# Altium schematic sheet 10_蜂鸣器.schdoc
size 309 x 223 mm; Symbol: Sheet-Symbol_A4; Device: Sheet-Symbol_A4; Company: 嘉立创EDA; Version: V1.0; Page Size: A4; @Project Name: 共享电动车中控; @Page Count: 11; @Update Date: 2024-11-20; @Create Date: 2024-10-05; @Schematic Name: SCH; @Page No: 10; @Page Name: 蜂鸣器; @Board Name: STM32F103C8T6; @Create Time: 01:14:23; @Update Time: 22:56:27
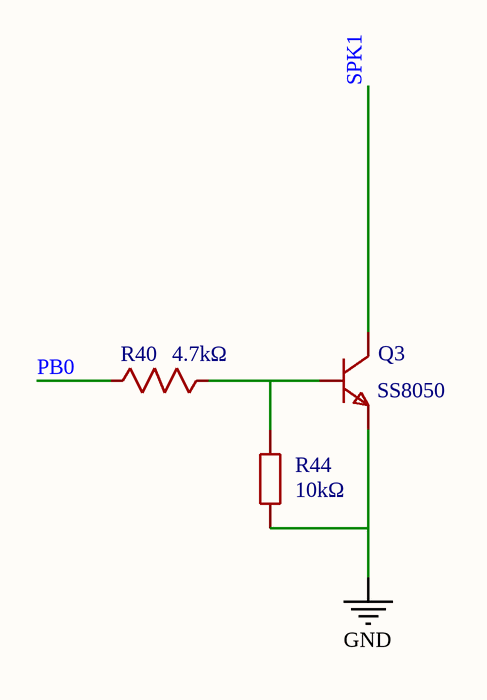
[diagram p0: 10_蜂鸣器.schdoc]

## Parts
Q3  SS8050  [SOT-23-3_L2.9-W1.3-P1.90-LS2.4-BR]  (value not drawn)
R40  4.7kΩ  [R0805]  (value not drawn)
R44  10kΩ  [R0805]

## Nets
GND: Q3.2(E) R44.2
PB0: R40.1
SPK1: Q3.3(C)
NetQ3_1: Q3.1(B) R40.2 R44.1

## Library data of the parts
Q3 = SS8050_C7420370: 晶体管类型:NPN;集电极电流(Ic):1.5A;集射极击穿电压(Vceo):25V;功率(Pd):300mW;直流电流增益(hFE@Ic,Vce):120@100mA,1.0V;; Manufacturer: 宏迦橙; Add into BOM: yes; Transistor Type: NPN; Collector Current (Ic): 1.5A; Collector-Emitter Breakdown Voltage (Vceo): 25V; Power Dissipation (Pd): 300mW; Transition Frequency (fT): 100MHz; Collector Cut-Off Current (Icbo): 100nA; Collector-Emitter Saturation Voltage (VCE(sat)@Ic,Ib): 500mV@800mA,80mA
R40 = 0805W8F4701T5E: 电阻类型:厚膜电阻;阻值:4.7kΩ;精度:±1%;功率:125mW;最大工作电压:150V;温度系数:±100ppm/℃;; Manufacturer: UNI-ROYAL(厚声); Symbol: 4.7k; Add into BOM: yes; Tolerance: ±1%; Power(Watts): 125mW; Overload Voltage (Max): 150V; Origin Footprint: R0603
R44 = 0805W8F1002T5E_C17414: 电阻类型:厚膜电阻;阻值:10kΩ;精度:±1%;功率:125mW;最大工作电压:150V;温度系数:±100ppm/℃;; Manufacturer: UNI-ROYAL(厚声); Symbol: RC0402FR-0710KL; Add into BOM: yes; Tolerance: ±1%; Power(Watts): 125mW; Overload Voltage (Max): 150V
